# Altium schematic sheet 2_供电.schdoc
size 497 x 243 mm
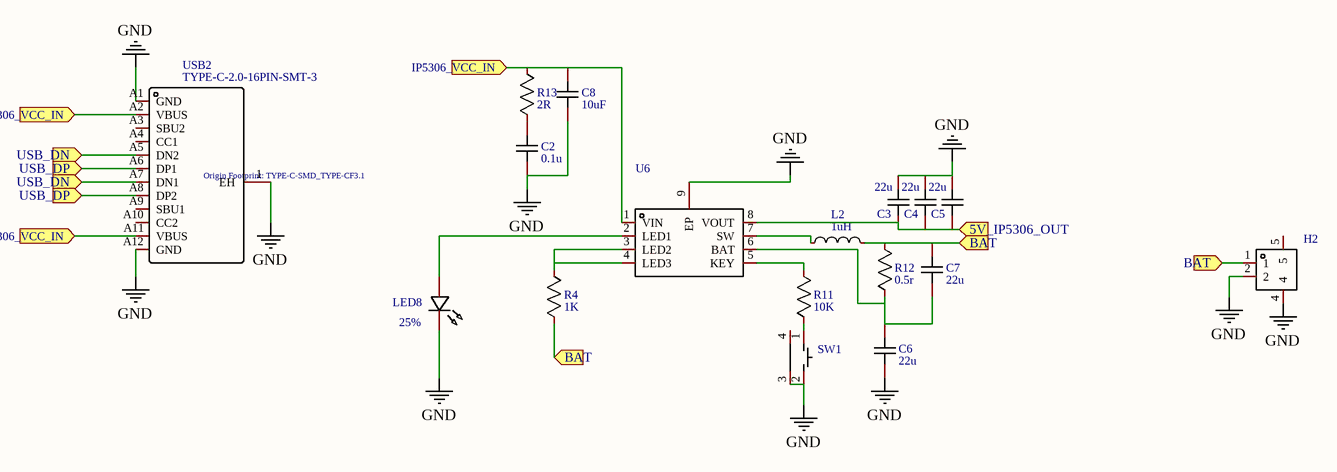
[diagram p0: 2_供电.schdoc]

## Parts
C2  0.1u  [C0805]
C3  22u  [C0805]
C4  22u  [C0805]
C5  22u  [C0805]
C6  22u  [C0805]
C7  22u  [C0805]
C8  10uF  [C0805]
H2  WAFER-PH2.0-2PWB  [CONN-SMD_2P-P2.00_XUNPU_WAFER-PH2.0-2PWB]  (value not drawn)
L2  Name: 1uH  (hidden comment: YPRH0704-1R0M)
LED8  Name: 25%  (hidden comment: 17-21SURC/S530-A3/TR8)
R4  Name: 1K  (hidden comment: 10K)
R11  10K
R12  0.5r
R13  2R
SW1  KH-6X6X6H-ZJ  [SW-TH_KH-6X6X6H-ZJ-A]  (value not drawn)
U6  IP5306  [ESOP-8_L4.9-W3.9-P1.27-LS6.0-BL-EP]  (value not drawn)
USB2  Origin Footprint: TYPE-C-SMD_TYPE-CF3.1  (hidden comment: TYPE-C-2.0-16PIN-SMT-3)

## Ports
5V_IP5306_OUT (in), BAT (in), IP5306_VCC_IN (in), USB_DN (in), USB_DP (in)

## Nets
GND: C2.1 C3.1 C4.1 C5.1 C6.2 C8.2 H2.2 H2.4 LED8.2 SW1.2 SW1.3 U6.9(EP) USB2.1(EH) USB2.A1(GND) USB2.A12(GND)
5V_IP5306_OUT: C3.2 C4.2 C5.2 U6.8(VOUT) ; port 5V_IP5306_OUT
BAT: C7.1 H2.1 L2.2 R4.2 R12.1 ; port BAT
IP5306_VCC_IN: C8.1 R13.2 U6.1(VIN) USB2.A2(VBUS) USB2.A11(VBUS) ; port IP5306_VCC_IN
USB_DN: USB2.A5(DN2) USB2.A7(DN1) ; port USB_DN
USB_DP: USB2.A6(DP1) USB2.A8(DP2) ; port USB_DP
NetC2_2: C2.2 R13.1
NetC6_1: C6.1 C7.2 R12.2 U6.6(BAT)
NetL2_1: L2.1 U6.7(SW)
NetLED8_1: LED8.1 U6.2(LED1)
NetR4_1: R4.1 U6.3(LED2) U6.4(LED3)
NetR11_1: R11.1 U6.5(KEY)
NetR11_2: R11.2 SW1.1

Not connected (* = marked no-connect by the designer): H2 5; SW1 4; USB2 A3(SBU2) A4(CC1) A9(SBU1) A10(CC2)

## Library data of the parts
C2 = 0.1u: Convert to PCB: yes
C3-C7 = 22u: Convert to PCB: yes
C8 = 10uF: Convert to PCB: yes
H2 = WAFER-PH2.0-2PWB: Manufacturer: XUNPU(讯普); Add into BOM: yes
L2 = YPRH0704-1R0M: Manufacturer: YJYCOIN; Convert to PCB: yes; Origin Footprint: IND-SMD_L7.3-W7.3
LED8 = 17-21SURC/S530-A3/TR8: Manufacturer: EVERLIGHT(台湾亿光); Symbol: 50%; Convert to PCB: yes; Origin Footprint: LED0805_RED
R4 = 10K: Convert to PCB: yes; Origin Footprint: R0805; NAME: 1
R11 = 10K: Convert to PCB: yes; Origin Footprint: R0805
R12 = 0.5r: Convert to PCB: yes; Origin Footprint: R0805
R13 = 2R: Convert to PCB: yes; Origin Footprint: R0805
SW1 = KH-6X6X6H-ZJ: 绝缘电阻:100MΩ;电路结构:单刀单掷;安装方式:卧插;按钮形状:圆形按钮;按钮/盖帽颜色:黑色;机械寿命:100000;引脚样式:PC引脚;开关长度:6mm;开关宽度:6mm;开关高度:6mm;带支架:是;; Manufacturer: kinghelm(金航标); Add into BOM: yes; Insulation Resistance: 100MΩ; Circuit: 单刀单掷; Actuator Style: 圆形按钮; Actuator/Cap Color: 黑色; Mechanical Life: 100000; Pin Style: PC引脚; Switch Length: 6mm; Strike Gundam: 是
U6 = IP5306: 充电电池的类型:-;电池单元组数:-;最大充电电流:-;充满的电池组电压:-;最大供应电压:-;; Manufacturer: INJOINIC(英集芯); Add into BOM: yes
USB2 = TYPE-C-2.0-16PIN-SMT-3: Manufacturer: CIKI(皓富); Convert to PCB: yes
